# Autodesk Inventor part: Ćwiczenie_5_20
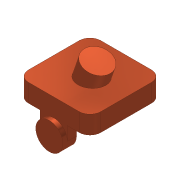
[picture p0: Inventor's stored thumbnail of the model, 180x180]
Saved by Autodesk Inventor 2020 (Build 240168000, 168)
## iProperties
Created: 2005-03
Part Number: Ćwiczenie_5_20
Document SubType Name: Modeling
Designer: F.Stasiak
Manufacturer: Standard
Standards Organization: Custom
Material: Miedź kuta
Mass: 571.266 g
Surface Area: 135.72 cm^2
Volume: 63.8999 cm^3
Density: 8.94 g/cm^3
Appearance: Miedź — satynowa
Manager: www.cadconsulting.pl
Company: Fabian Stasiak CAD Consulting
Author: F.Stasiak
Subject: Zbiór ćwiczeń. Autodesk Inventor 2020. Kurs podstawowy
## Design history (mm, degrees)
sketch "Szkic1"
  geometry: L1 (-40, 40)-(40, 40); L2 (40, 40)-(40, -40); L3 (40, -40)-(-40, -40); L4 (-40, -40)-(-40, 40); L5 (-40, 0)-(40, 0); 2 further points
  constraints: 10 end point, 3 midpoint, 2 parallel, 1 coincident, 1 horizontal, 1 perpendicular
  dimensions: "d30" = 80 distance of L2.end L3.end; "d31" = 80 distance of L3.end L1.start
extrude "Wyciągnięcie proste1" new body sketch "Szkic1" stored distance "d1" = 20; taper "d2" = 0 deg
fillet "Zaokrąglenie1" dims "d3" = 12
sketch "Szkic2"
  geometry: L1 (0, 4.884)-(-8.139, 28.521); L2 (-8.139, 28.521)-(-22.322, 23.638); L3 (25, 10)-(25, 0) reference; L4 (25, 0)-(-25, 0) reference; L5 (-25, 0)-(-25, 10) reference; L6 (-25, 10)-(25, 10) reference; L7 (-22.322, 23.638)-(-14.183, 0); L8 (-14.183, 0)-(0, 4.884); 1 further point
  constraints: 16 end point, 3 perpendicular, 2 horizontal, 2 vertical, 1 point on line, 4 other
  dimensions: "d4" = 109 deg angle of L1 L6; "d5" = 25 distance of L2.end L7.end; "d6" = 30 diameter of L7 L1; "d16" = 0 horizontal distance of point (0, 0) L1.start
revolve "Obrót1" sketch "Szkic2" stored, may be unused: angle "d7" = 90 deg
sketch "Szkic4"
  geometry: L1 (-13, 20)-(-13, 35); L2 (-43, 35)-(-43, 20); L3 (0, 20)-(-56, 20) reference; A1 r 15 centre (-28, 35) between (-13, 35) and (-43, 35); 3 further points
  constraints: 4 end point, 2 perpendicular, 2 point on circle, 2 point on line, 2 tangent, 2 vertical alignment, 1 centre point
  dimensions: "d34" = 15 radius of A1; "d38" = 15 distance of L2.start L2.end
extrude "Wyciągnięcie proste2" join sketch "Szkic4" distance "d36" = 10; taper "d37" = 0 deg
sketch "Szkic5"
  geometry: C1 r 15 at (28, -35); A1 r 15 centre (28, -35) between (13, -35) and (43, -35) reference; 3 further points
  constraints: 1 centre point, 1 coincident
extrude "Wyciągnięcie proste3" join sketch "Szkic5" distance "d39" = 5; taper "d40" = 0 deg
mirror "Odbij1"
node "Bryła1"
node "Korpusy bryłowe"
node "Korpusy powierzchniowe"
